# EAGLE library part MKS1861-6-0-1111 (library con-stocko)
Serie MKS 1850 Lötstifte In-line, Raster 2.5 mm, Stiftwannen, stehend, mit Rastlasche Source: http://www.stocko.de/de/index.php?seite=ka_rfk2_mks1850.html&rubrik=Katalog+-+RFK+2 rfk_1850.pdf
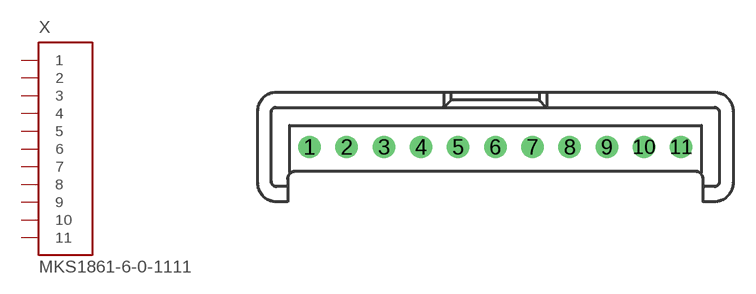
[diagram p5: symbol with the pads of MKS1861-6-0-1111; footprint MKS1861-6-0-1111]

Designator prefix X

## MKS1861-6-0-1111 (OC_FARNELL: unknown; OC_NEWARK: unknown)  [MKS1861-6-0-1111]
1  1  in
2  2  in
3  3  in
4  4  in
5  5  in
6  6  in
7  7  in
8  8  in
9  9  in
10  10  in
11  11  in

## Footprint MKS1861-6-0-1111 (pad centres in mm)
Serie MKS 1850 Lötstifte In-line, Raster 2.5 mm, Stiftwannen, stehend, mit Rastlasche Source: http://www.stocko.de/de/index.php?seite=ka_rfk2_mks1850.html&rubrik=Katalog+-+RFK+2 rfk_1850.pdf
drill 1 pad 1.422 round: 1 -12.5,0; 2 -10,0; 3 -7.5,0; 4 -5,0; 5 -2.5,0; 6 0,0; 7 2.5,0; 8 5,0; 9 7.5,0; 10 10,0; 11 12.5,0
